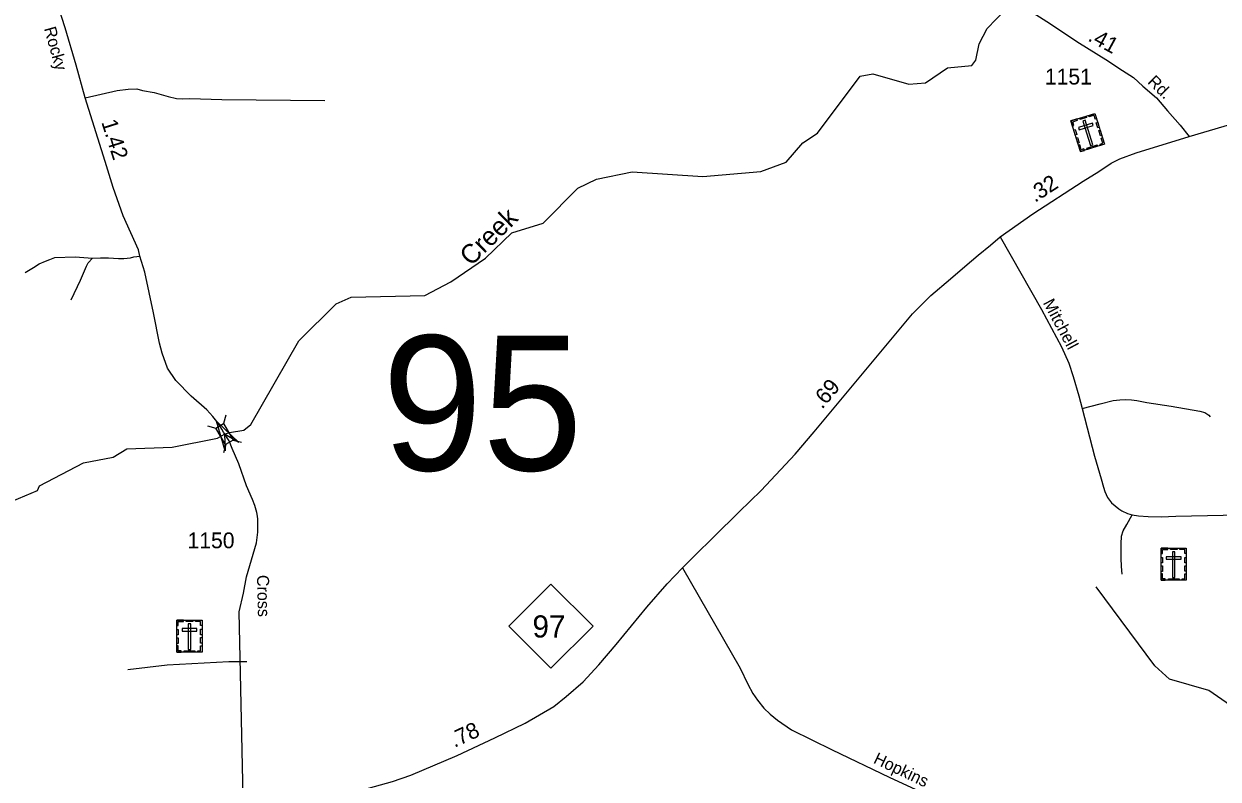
# Model space of a CAD drawing. Extents: x 2220236 to 2384410, y 720751 to 894131.
# Drawn here: x 2230421 to 2239863, y 763290 to 769263 of the extents above; entities that cross this region are included whole.
import ezdxf

# ---------------------------------------------------------------- set-up
doc = ezdxf.new("R2010")
doc.units = 0
for name, color, linetype in [('Exist Cultural Cemetery CELL', 7, 'Continuous'), ('Exist Hydrographic Creek Single Shore', 7, 'Continuous'), ('Exist Hydrographic Creek Single Shore Label', 7, 'Continuous'), ('Exist Road Non-System Type 51', 7, 'Continuous'), ('Exist Road Primary NC Attributed', 7, 'Continuous'), ('Exist Road Primary NC Service Mileage Hundredths English Label', 7, 'Continuous'), ('Exist Road Primary NC Shield CELL', 7, 'Continuous'), ('Exist Road Primary NC Shield Number Label', 7, 'Continuous'), ('Exist Road Secondary Mileage Hundredths English Label', 7, 'Continuous'), ('Exist Road Secondary Structure Standard Bridge Attributed CELL', 7, 'Continuous'), ('Exist Road Secondary Structure Standard Bridge CELL', 7, 'Continuous'), ('Exist Road Secondary Structure Standard Bridge Number Label', 7, 'Continuous'), ('Exist Road Secondary Type 51 Attributed', 7, 'Continuous'), ('Exist Road Secondary Type 51 Label', 7, 'Continuous'), ('Exist Road Secondary Type 51 Number Label', 7, 'Continuous')]:
    doc.layers.add(name, color=color, linetype=linetype)

msp = doc.modelspace()

# ---------------------------------------------------------------- linework, layer by layer
at = {"layer": 'Exist Cultural Cemetery CELL'}
for points in [[(2238699.5, 768495.7), (2238889.8, 768554.4), (2238964.9, 768311.1), (2238774.7, 768252.4)], [(2238712.3, 768454.3), (2238723.2, 768457.6), (2238713.7, 768488.4), (2238752.4, 768500.3), (2238749.1, 768511), (2238699.5, 768495.7)], [(2238770.3, 768517.5), (2238819.8, 768532.8), (2238823.2, 768521.9), (2238773.7, 768506.6)], [(2238812.3, 768499.8), (2238794.5, 768494.3), (2238854.4, 768300.6), (2238872.2, 768306.1)], [(2238902.6, 768513), (2238891.8, 768509.7), (2238882.3, 768540.4), (2238843.5, 768528.4), (2238840.2, 768539.1), (2238889.8, 768554.4)], [(2238734.2, 768383.4), (2238721.4, 768424.8), (2238732.3, 768428.2), (2238745.1, 768386.8)], [(2238758.6, 768442.7), (2238764.1, 768424.8), (2238876.6, 768459.6), (2238871.1, 768477.4)], [(2238913.3, 768439.8), (2238900.5, 768481.2), (2238911.4, 768484.6), (2238924.2, 768443.2)], [(2238932.7, 768376.8), (2238919.9, 768418.2), (2238930.8, 768421.6), (2238943.6, 768380.2)], [(2238754, 768319.2), (2238741.2, 768360.6), (2238752.1, 768363.9), (2238764.9, 768322.6)], [(2238806.3, 768262.2), (2238802.9, 768273.2), (2238781.9, 768266.7), (2238769.9, 768305.3), (2238759.3, 768302), (2238774.6, 768252.4)], [(2238826.2, 768280.3), (2238907.3, 768305.3), (2238910.6, 768294.5), (2238829.6, 768269.4)], [(2238933.3, 768301.4), (2238929.9, 768312.3), (2238950.9, 768318.8), (2238939, 768357.4), (2238949.6, 768360.7), (2238964.9, 768311.1)], [(2239412.8, 765116.6), (2239611.9, 765116.6), (2239611.9, 764861.9), (2239412.8, 764861.9)], [(2239412.8, 765073.2), (2239424.1, 765073.2), (2239424.1, 765105.4), (2239464.7, 765105.4), (2239464.7, 765116.6), (2239412.8, 765116.6)], [(2239486.9, 765116.5), (2239538.7, 765116.5), (2239538.7, 765105.1), (2239486.9, 765105.1)], [(2239612, 765073.2), (2239600.6, 765073.2), (2239600.6, 765105.4), (2239560, 765105.4), (2239560, 765116.5), (2239611.9, 765116.5)], [(2239412.8, 764999.1), (2239412.8, 765042.4), (2239424.2, 765042.4), (2239424.2, 764999.1)], [(2239453.6, 765048.5), (2239453.6, 765029.8), (2239571.3, 765029.8), (2239571.3, 765048.5)], [(2239521.8, 765087.3), (2239503.1, 765087.3), (2239503.1, 764884.5), (2239521.8, 764884.5)], [(2239600.5, 765000.1), (2239600.5, 765043.4), (2239611.9, 765043.4), (2239611.9, 765000.1)], [(2239445.9, 764862), (2239445.9, 764873.5), (2239423.9, 764873.5), (2239423.9, 764913.9), (2239412.7, 764913.9), (2239412.7, 764862)], [(2239412.8, 764931.9), (2239412.8, 764975.2), (2239424.1, 764975.2), (2239424.1, 764931.9)], [(2239578.7, 764861.9), (2239578.7, 764873.4), (2239600.7, 764873.4), (2239600.7, 764913.8), (2239611.9, 764913.8), (2239611.9, 764861.9)], [(2239600.5, 764934.2), (2239600.5, 764977.5), (2239611.9, 764977.5), (2239611.9, 764934.2)], [(2239470.2, 764873.4), (2239555.1, 764873.4), (2239555.1, 764862), (2239470.2, 764862)], [(2231631, 764547.8), (2231830.1, 764547.8), (2231830.1, 764293.1), (2231631, 764293.1)], [(2231631, 764504.5), (2231642.4, 764504.5), (2231642.4, 764536.7), (2231682.9, 764536.6), (2231682.9, 764547.8), (2231631, 764547.8)], [(2231705.1, 764547.8), (2231756.9, 764547.8), (2231756.9, 764536.4), (2231705.1, 764536.4)], [(2231830.2, 764504.4), (2231818.8, 764504.4), (2231818.8, 764536.6), (2231778.3, 764536.6), (2231778.3, 764547.7), (2231830.2, 764547.7)], [(2231631, 764430.3), (2231631, 764473.6), (2231642.4, 764473.6), (2231642.4, 764430.3)], [(2231671.8, 764479.7), (2231671.8, 764461), (2231789.6, 764461), (2231789.6, 764479.7)], [(2231740, 764518.5), (2231721.4, 764518.5), (2231721.4, 764315.7), (2231740, 764315.7)], [(2231818.8, 764431.3), (2231818.8, 764474.7), (2231830.2, 764474.7), (2231830.2, 764431.3)], [(2231631, 764363.1), (2231631, 764406.4), (2231642.4, 764406.4), (2231642.4, 764363.1)], [(2231664.1, 764293.2), (2231664.1, 764304.7), (2231642.1, 764304.7), (2231642.1, 764345.1), (2231631, 764345.1), (2231631, 764293.2)], [(2231797, 764293.1), (2231797, 764304.6), (2231819, 764304.6), (2231819, 764345), (2231830.1, 764345), (2231830.1, 764293.1)], [(2231818.7, 764365.4), (2231818.7, 764408.7), (2231830.1, 764408.7), (2231830.1, 764365.4)], [(2231688.5, 764304.6), (2231773.3, 764304.6), (2231773.3, 764293.2), (2231688.5, 764293.2)]]:
    msp.add_lwpolyline(points, close=True, dxfattribs=at)
at = {"layer": 'Exist Hydrographic Creek Single Shore'}
for points in [[(2230329.9, 765487.8), (2230529.8, 765572.2), (2230545.8, 765608), (2230893.8, 765791.1), (2231126.9, 765835.5), (2231235, 765902.2), (2231592.8, 765914.4), (2231951.9, 765987.2), (2232007.7, 766017), (2232047.8, 766030.4), (2232161.3, 766049.8), (2232215.9, 766095.2), (2232593.9, 766756.5), (2232891, 767048.9), (2233007.9, 767102.3), (2233590.8, 767113.2), (2233797.9, 767223.8), (2234070.9, 767408.5), (2234278, 767610.8), (2234526.9, 767687.7), (2234800.1, 767964.2), (2234948.9, 768033.3), (2235231.9, 768093.1), (2235790.1, 768055.4), (2236247.9, 768095.1), (2236448.1, 768169.8), (2236579.9, 768321.2), (2236696, 768397.5), (2237033.1, 768849.8), (2237133, 768867.4), (2237417, 768786.2), (2237550, 768796.5), (2237724.1, 768914.3), (2237916.1, 768933.3), (2237949.1, 768975.3), (2237973.1, 769106), (2238038.1, 769226), (2238250.3, 769448)], [(2241363, 762955.1), (2240910, 763335), (2240659, 763497.6), (2240524.9, 763546.3), (2240332, 763711), (2240065, 763801.7), (2239789, 763991.1), (2239480, 764079.5), (2239362.1, 764186.9), (2238899.1, 764809.7)]]:
    msp.add_lwpolyline(points, dxfattribs=at)
at = {"layer": 'Exist Road Non-System Type 51'}
for points in [[(2230907, 768676.5), (2231158.4, 768736.5), (2231246.2, 768747.3), (2231314.2, 768747.9), (2231360.3, 768736.1), (2231452.4, 768720.8), (2231506.4, 768703.3), (2231562.7, 768687.8), (2231626.8, 768672.2), (2231676.7, 768670.8), (2231734.7, 768673.2), (2231986.5, 768665.3), (2232800.3, 768655.9)], [(2230430.4, 767295.2), (2230498.2, 767335.8), (2230541.9, 767364.1), (2230592.7, 767386.2), (2230625.6, 767400.1), (2230665.5, 767416), (2230827.3, 767421.3), (2230963.6, 767410.5)], [(2230796, 767080.3), (2230868.8, 767234.8), (2230915.8, 767345.2), (2230930.7, 767372.4), (2230963.6, 767410.5)], [(2230963.6, 767410.5), (2231026, 767412.3), (2231090.1, 767412.3), (2231169.3, 767407.2), (2231211.2, 767407.5), (2231265.1, 767412), (2231291.1, 767420.1), (2231337, 767426.5)], [(2238789, 766219.9), (2238929.6, 766257.3), (2239033.6, 766283.4), (2239087.4, 766290.3), (2239129, 766292), (2239179.2, 766290.3), (2239220.8, 766283.4), (2239300.5, 766267.7), (2239491.2, 766238.3), (2239720, 766198.4), (2239758.1, 766188), (2239791, 766168.9), (2239799.7, 766155)], [(2239104.7, 764911.5), (2239099.5, 764970.5), (2239097.8, 765036.4), (2239097.8, 765150.8), (2239099.5, 765211.5), (2239113.4, 765253.2), (2239142.8, 765303.5), (2239183.2, 765380.8)], [(2231244.4, 764157.8), (2231553.8, 764194.2), (2232042.5, 764220.2), (2232182.8, 764218.7)]]:
    msp.add_lwpolyline(points, dxfattribs=at)
at = {"layer": 'Exist Road Primary NC Attributed'}
for points in [[(2239633.6, 768371.7), (2240991.9, 768772.1), (2241286.5, 768858.8), (2241447.4, 768905.6), (2241515.4, 768919.7), (2241601.2, 768937.5), (2241672.3, 768952.1), (2241760.7, 768963.7), (2241855, 768970.9), (2241998.6, 768970.9), (2242133.5, 768966.6), (2242433.7, 768932.1), (2242683.3, 768901.3), (2242816.7, 768892.5), (2243404.2, 768908.5)], [(2238141, 767577.2), (2238399.3, 767761), (2238796.2, 768019.4), (2238919.2, 768095.7), (2239018, 768159.9), (2239087.4, 768194.6), (2239214.8, 768242.3), (2239633.6, 768371.7)], [(2235627.8, 764961.8), (2235724.9, 765057.2), (2235875.7, 765206.3), (2236076.8, 765404.1), (2236249.9, 765573.4), (2236519.4, 765859.3), (2236670, 766036.6), (2237222.4, 766699.6), (2237446, 766968.4), (2237591.6, 767114.1), (2237747.6, 767245.9), (2237862, 767343), (2237966, 767433.2), (2238063, 767511.3), (2238141, 767577.2)], [(2232159.5, 762906.5), (2232463.7, 763026.2), (2232663.6, 763097.1), (2232793.3, 763126.3), (2233145.9, 763218.8), (2233336.5, 763270.8), (2233480.4, 763321.1), (2233846.1, 763477.2), (2234145.9, 763616), (2234383.8, 763731), (2234610.4, 763864), (2234709.2, 763942), (2234842.7, 764058.2), (2234967.5, 764193.5), (2235104.2, 764354.4), (2235347.1, 764649.6), (2235506.5, 764835.2), (2235627.8, 764961.8)]]:
    msp.add_lwpolyline(points, dxfattribs=at)
at = {"layer": 'Exist Road Primary NC Shield CELL'}
msp.add_lwpolyline([(2234255.6, 764499.4), (2234588.6, 764832.4), (2234921.6, 764499.4), (2234588.6, 764166.4)], close=True, dxfattribs=at)
at = {"layer": 'Exist Road Secondary Structure Standard Bridge Attributed CELL'}
msp.add_lwpolyline([(2232011.7, 765887.1), (2231945.2, 766121.7), (2232120.1, 765951.8), (2232007.7, 766017)], close=True, dxfattribs=at)
at = {"layer": 'Exist Road Secondary Structure Standard Bridge CELL'}
for p, q in [((2232017.4, 766167.9), (2232000.1, 766101.1)), ((2231872.5, 766082.7), (2231939.2, 766065.4)), ((2232076.4, 765970.7), (2232143.2, 765953.4)), ((2232016.9, 765935.7), (2231999.6, 765869))]:
    msp.add_line(p, q, dxfattribs=at)
msp.add_lwpolyline([(2232000.1, 766101.1), (2232076.7, 765970.9), (2232015.8, 765935.1), (2231939.2, 766065.4)], close=True, dxfattribs=at)
at = {"layer": 'Exist Road Secondary Type 51 Attributed'}
for points in [[(2232000.6, 766032.7), (2231985.8, 766056.3), (2231957.4, 766104.1), (2231914.9, 766157.8), (2231868.6, 766209.3), (2231743.5, 766319.6), (2231622.2, 766441), (2231556.4, 766539.9), (2231515.2, 766658.3), (2231494.6, 766738.1), (2231446.5, 766977.6), (2231378, 767298.9), (2231337, 767426.5), (2231326.6, 767474.3), (2231206.2, 767743.5), (2231128.2, 767969), (2231063.1, 768174), (2230907, 768676.5), (2230835, 768935.9), (2230748.7, 769231.6), (2230674.7, 769462.2), (2230625.6, 769635.7), (2230564.4, 769829), (2230519.9, 770008.5)], [(2238265.3, 769437.4), (2238508.5, 769282), (2238768, 769110.3), (2238976.4, 768982), (2239106.4, 768893.5), (2239193.9, 768837.8), (2239268.5, 768770.5), (2239375.1, 768678.5), (2239464, 768574.1), (2239562.8, 768461.1), (2239633.6, 768371.7)], [(2238141, 767577.2), (2238467.2, 767004.8), (2238625.6, 766708.2), (2238682.6, 766578.7), (2238717.4, 766475), (2238762.6, 766321.5), (2238789, 766219.9), (2238886.4, 765844.7), (2238939.9, 765665.2), (2238956.3, 765599.3), (2238968.8, 765563.4), (2238989, 765517.6), (2239021.3, 765474), (2239077.8, 765428.4), (2239101.9, 765412.5), (2239148, 765391), (2239183.2, 765380.8), (2239234.2, 765371.6), (2239310.2, 765366.3), (2239412.2, 765365.2), (2239528.1, 765370), (2241272.9, 765406.3)], [(2232159.5, 762906.5), (2232123, 764613.7), (2232157.7, 764759.8), (2232182.1, 764888.5), (2232261.1, 765157.1), (2232270.2, 765243.1), (2232271.5, 765345), (2232269.2, 765369.1), (2232263, 765397), (2232246.6, 765452.7), (2232228.1, 765500.7), (2232181.4, 765608.2), (2232119.6, 765783.7), (2232069.4, 765905.1), (2232043.4, 765964.1), (2232000.6, 766032.7)], [(2235627.8, 764961.8), (2236083.4, 764166.5), (2236144.5, 764041.1), (2236184.9, 763967.5), (2236221.4, 763913.8), (2236271.9, 763850.1), (2236322.1, 763804.7), (2236380.5, 763757.1), (2236489.5, 763679.4), (2236811.7, 763522.4), (2237262.6, 763305.2), (2238163.6, 762887.5)]]:
    msp.add_lwpolyline(points, dxfattribs=at)

# ---------------------------------------------------------------- texts
at = {"layer": 'Exist Hydrographic Creek Single Shore Label'}
msp.add_text('Creek', height=150, rotation=44.33295, dxfattribs=at).set_placement((2233956, 767340.9))
at = {"layer": 'Exist Road Primary NC Service Mileage Hundredths English Label'}
for s, rotation, p in [('.32', 33.067, (2238415.3, 767846)), ('.69', 50.19628, (2236733.2, 766210.1)), ('.78', 24.831, (2233825.4, 763536.5))]:
    msp.add_text(s, height=125, rotation=rotation, dxfattribs=at).set_placement(p)
at = {"layer": 'Exist Road Primary NC Shield Number Label'}
msp.add_text('97', height=175, dxfattribs=at).set_placement((2234442.7, 764409.7))
at = {"layer": 'Exist Road Secondary Mileage Hundredths English Label'}
for s, rotation, p in [('.41', 331.4621, (2238826.7, 769133.4)), ('1.42', 287.55715, (2231032.4, 768486))]:
    msp.add_text(s, height=125, rotation=rotation, dxfattribs=at).set_placement(p)
at = {"layer": 'Exist Road Secondary Structure Standard Bridge Number Label'}
msp.add_text('95', height=1066.27, dxfattribs=at).set_placement((2233253.7, 765731.1))
at = {"layer": 'Exist Road Secondary Type 51 Label'}
for s, rotation, p in [('Rocky', 285.55656, (2230579.8, 769226.3)), ('Rd.', 316.05354, (2239299.6, 768797.4)), ('Mitchell', 298.11402, (2238476.5, 767057)), ('Cross', 271.47784, (2232263.8, 764903.4)), ('Hopkins', 334.62169, (2237131.5, 763419.5))]:
    msp.add_text(s, height=95, rotation=rotation, dxfattribs=at).set_placement(p)
at = {"layer": 'Exist Road Secondary Type 51 Number Label'}
for s, p in [('1151', (2238493.6, 768783.1)), ('1150', (2231715, 765115.4))]:
    msp.add_text(s, height=125, dxfattribs=at).set_placement(p)

doc.saveas('drawing.dxf')
